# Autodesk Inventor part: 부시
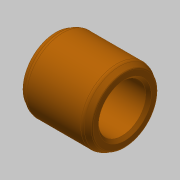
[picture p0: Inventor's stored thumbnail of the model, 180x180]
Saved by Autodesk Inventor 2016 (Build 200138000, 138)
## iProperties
Created: 2018-11
Part Number: 부시
Material: 강철, 연강
Document SubType Name: Modeling
Designer: mduedu
Density: 1 g/cm^3
Appearance: 주황색
Author: mduedu
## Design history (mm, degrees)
sketch "스케치1"
  geometry: C1 r 8.5 at (0, 0); C2 r 13 at (0, 0); 1 further point
  constraints: 2 centre point, 2 coincident
  dimensions: "d0" = 17 diameter of C1; "d1" = 26 diameter of C2
extrude "돌출1" new body sketch "스케치1" distance "d2" = 25; taper "d3" = 0 deg
chamfer "모따기4" distance "d14" = 1; stored, may be unused: second distance "d15" = 2, angle "d16" = 15 deg
chamfer "모따기5" distance "d17" = 2.3; stored, may be unused: second distance "d18" = 2, angle "d19" = 30 deg
chamfer "모따기6" distance "d20" = 2.3; stored, may be unused: second distance "d21" = 2, angle "d22" = 30 deg
fillet "모깎기2" dims "d23" = 2, "d24" = 0.5
fillet "모깎기3" dims "d25" = 2, "d26" = 0.5
node "솔리드1"
